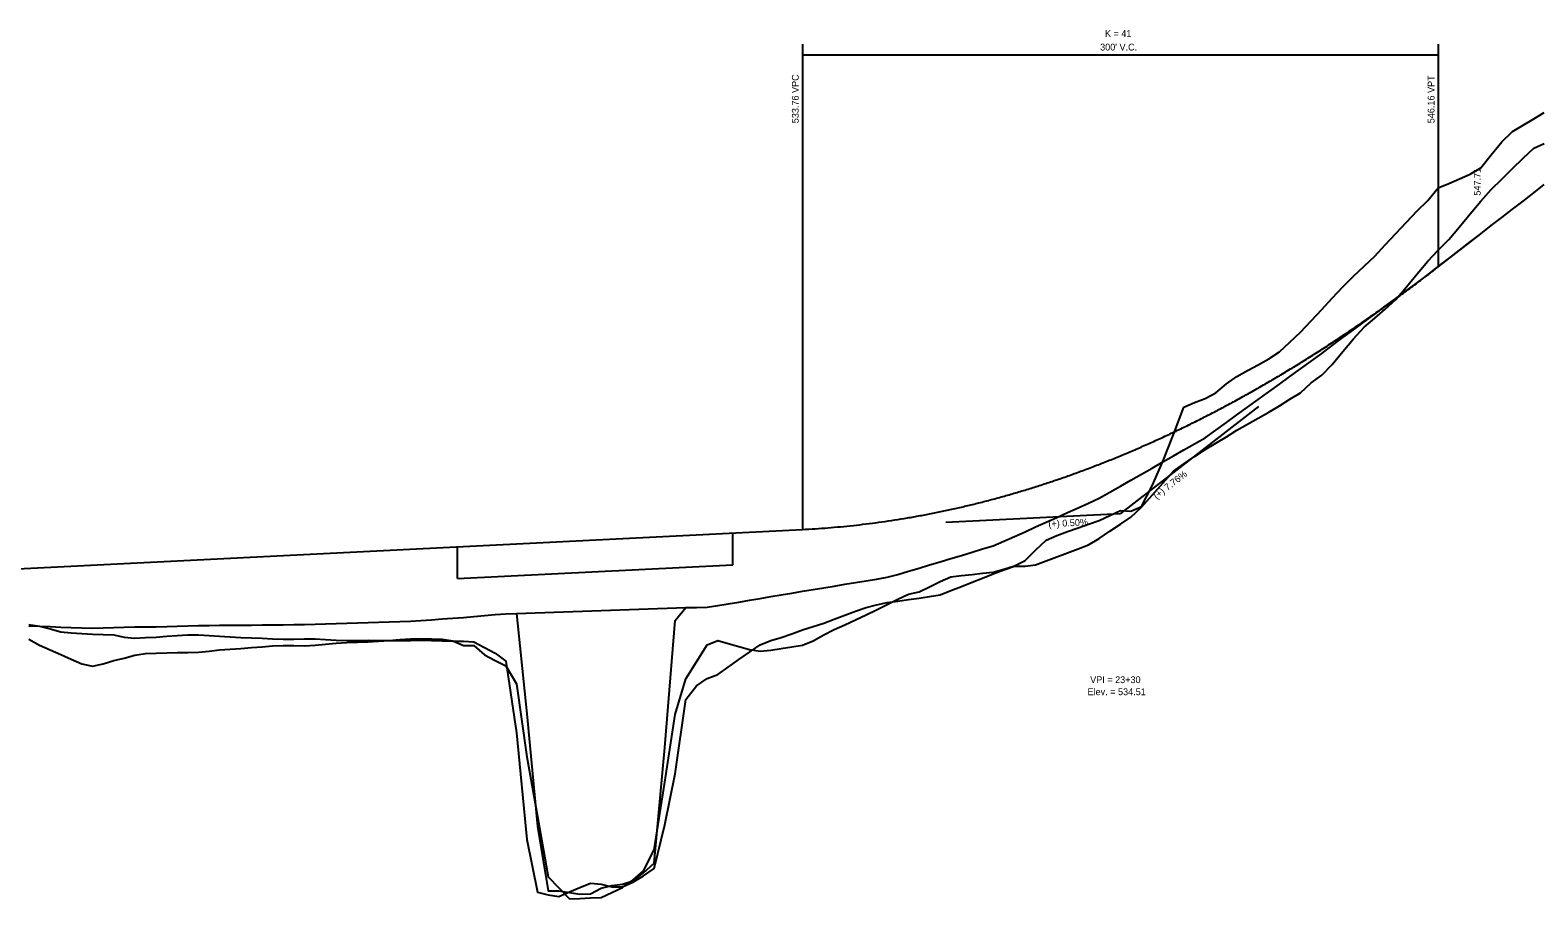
# Model space of a CAD drawing. Extents: x 1511486 to 1516886, y 901686 to 906985.
# Drawn here: x 1513890 to 1514602, y 905350 to 905760 of the extents above; entities that cross this region are included whole.
import ezdxf

# ---------------------------------------------------------------- set-up
doc = ezdxf.new("R2010")
doc.units = 0
for name, color, linetype in [('RD_DDB_GradeTX', 7, 'Continuous'), ('RD_DDB_Profile_EX', 7, 'Continuous'), ('RD_DDB_Profile_Lbl', 7, 'Continuous'), ('RD_DDB_Profile_PR', 7, 'Continuous'), ('RD_DDB_StripGrade', 7, 'Continuous'), ('RD_DDB_VCLbl', 7, 'Continuous'), ('RD_Sketch1', 7, 'Continuous'), ('RD_Sketch2', 7, 'Continuous'), ('RD_Sketch3', 7, 'Continuous')]:
    doc.layers.add(name, color=color, linetype=linetype)

msp = doc.modelspace()

# ---------------------------------------------------------------- linework, layer by layer
at = {"layer": 'RD_DDB_GradeTX'}
for p in [(1514469.77, 905582.08), (1514322.39, 905527.44)]:
    msp.add_line(p, (1514404.68, 905531.55), dxfattribs=at)
at = {"layer": 'RD_DDB_Profile_EX'}
for points in [[(1514574.68, 905663.52), (1514579.68, 905667.38), (1514584.68, 905671.23), (1514589.68, 905675.09), (1514594.68, 905678.97), (1514599.68, 905682.91), (1514604.68, 905686.86)], [(1514074.68, 905481.08), (1514079.68, 905481.48), (1514084.68, 905481.88), (1514089.68, 905482.21), (1514094.68, 905482.58), (1514099.68, 905482.99), (1514104.68, 905483.42), (1514109.68, 905483.86), (1514114.68, 905484.17), (1514119.68, 905484.46), (1514124.68, 905437.02), (1514129.68, 905383.98), (1514134.68, 905353.54), (1514139.68, 905353.56), (1514144.68, 905352.76), (1514149.68, 905351.96), (1514154.68, 905352.1), (1514159.68, 905354.75), (1514164.68, 905356.11), (1514169.68, 905356.62), (1514174.68, 905358.34), (1514179.68, 905361.97), (1514184.68, 905366.53), (1514189.68, 905421.12), (1514194.68, 905481.14), (1514199.68, 905487.19), (1514204.68, 905487.3), (1514209.68, 905487.41), (1514214.68, 905488.1), (1514219.68, 905488.96), (1514224.68, 905489.81), (1514229.68, 905490.66), (1514234.68, 905491.51), (1514239.68, 905492.36), (1514244.68, 905493.22), (1514249.68, 905494.04), (1514254.68, 905494.87), (1514259.68, 905495.69), (1514264.68, 905496.51), (1514269.68, 905497.34), (1514274.68, 905498.16), (1514279.68, 905498.98), (1514284.68, 905499.81), (1514289.68, 905500.63), (1514294.68, 905501.46), (1514299.68, 905502.83), (1514304.68, 905504.33), (1514309.68, 905505.83), (1514314.68, 905507.33), (1514319.68, 905508.83), (1514324.68, 905510.33), (1514329.68, 905511.83), (1514334.68, 905513.33), (1514339.68, 905514.83), (1514344.68, 905516.32), (1514349.68, 905518.46), (1514354.68, 905520.71), (1514359.68, 905522.97), (1514364.68, 905525.21), (1514369.68, 905527.47), (1514374.68, 905529.72), (1514379.68, 905531.98), (1514384.68, 905534.24), (1514389.68, 905536.5), (1514394.68, 905538.75), (1514399.68, 905541.56), (1514404.68, 905544.42), (1514409.68, 905547.28), (1514414.68, 905550.15), (1514419.68, 905553.01), (1514424.68, 905555.87), (1514429.68, 905558.74), (1514434.68, 905561.6), (1514439.68, 905564.46), (1514444.68, 905567.32), (1514449.68, 905570.88), (1514454.68, 905574.49), (1514459.68, 905578.11), (1514464.68, 905581.72), (1514469.68, 905585.33), (1514474.68, 905588.95), (1514479.68, 905592.56), (1514484.68, 905596.17), (1514489.68, 905599.79), (1514494.68, 905603.41), (1514499.68, 905607.13), (1514504.68, 905610.84), (1514509.68, 905614.54), (1514514.68, 905618.23), (1514519.68, 905621.93), (1514524.68, 905625.63), (1514529.68, 905629.34), (1514534.68, 905633.04), (1514539.68, 905636.74), (1514544.68, 905640.34), (1514549.68, 905644.2), (1514554.68, 905648.06), (1514559.68, 905651.92), (1514564.68, 905655.81), (1514569.68, 905659.67), (1514574.68, 905663.52)], [(1513889.68, 905478.58), (1513894.68, 905478.39), (1513899.68, 905478.2), (1513904.68, 905478), (1513909.68, 905477.79), (1513914.68, 905477.58), (1513919.68, 905477.53), (1513924.68, 905477.61), (1513929.68, 905477.79), (1513934.68, 905477.95), (1513939.68, 905478.03), (1513944.68, 905478.05), (1513949.68, 905478.18), (1513954.68, 905478.31), (1513959.68, 905478.44), (1513964.68, 905478.56), (1513969.68, 905478.67), (1513974.68, 905478.76), (1513979.68, 905478.83), (1513984.68, 905478.9), (1513989.68, 905478.89), (1513994.68, 905478.95), (1513999.68, 905479.01), (1514004.68, 905479.06), (1514009.68, 905479.11), (1514014.68, 905479.16), (1514019.68, 905479.2), (1514024.68, 905479.31), (1514029.68, 905479.46), (1514034.68, 905479.62), (1514039.68, 905479.79), (1514044.68, 905479.95), (1514049.68, 905480.1), (1514054.68, 905480.26), (1514059.68, 905480.41), (1514064.68, 905480.57), (1514069.68, 905480.72), (1514074.68, 905481.08)]]:
    msp.add_lwpolyline(points, dxfattribs=at)
at = {"layer": 'RD_DDB_Profile_PR'}
for p, q in [((1514554.68, 905648), (1514574.68, 905663.52)), ((1513874.68, 905505.05), (1514254.68, 905524.05))]:
    msp.add_line(p, q, dxfattribs=at)
msp.add_spline([(1514254.68, 905524.05), (1514260.68, 905524.4), (1514266.68, 905524.83), (1514272.68, 905525.35), (1514278.68, 905525.95), (1514284.68, 905526.64), (1514290.68, 905527.42), (1514296.68, 905528.29), (1514302.68, 905529.24), (1514308.68, 905530.28), (1514314.68, 905531.41), (1514320.68, 905532.63), (1514326.68, 905533.93), (1514332.68, 905535.32), (1514338.68, 905536.8), (1514344.68, 905538.36), (1514350.68, 905540.01), (1514356.68, 905541.75), (1514362.68, 905543.57), (1514368.68, 905545.49), (1514374.68, 905547.49), (1514380.68, 905549.57), (1514386.68, 905551.75), (1514392.68, 905554.01), (1514398.68, 905556.36), (1514404.68, 905558.79), (1514410.68, 905561.31), (1514416.68, 905563.92), (1514422.68, 905566.62), (1514428.68, 905569.4), (1514434.68, 905572.27), (1514440.68, 905575.23), (1514446.68, 905578.28), (1514452.68, 905581.41), (1514458.68, 905584.63), (1514464.68, 905587.94), (1514470.68, 905591.33), (1514476.68, 905594.81), (1514482.68, 905598.38), (1514488.68, 905602.04), (1514494.68, 905605.78), (1514500.68, 905609.61), (1514506.68, 905613.53), (1514512.68, 905617.53), (1514518.68, 905621.62), (1514524.68, 905625.8), (1514530.68, 905630.07), (1514536.68, 905634.42), (1514542.68, 905638.86), (1514548.68, 905643.38), (1514554.68, 905648)], degree=3, dxfattribs=at)
at = {"layer": 'RD_DDB_VCLbl'}
for p, q in [((1514254.68, 905753), (1514254.68, 905524.05)), ((1514554.68, 905753), (1514554.68, 905648)), ((1514254.68, 905748), (1514554.68, 905748))]:
    msp.add_line(p, q, dxfattribs=at)
at = {"layer": 'RD_Sketch1'}
msp.add_line((1514119.68, 905484.46), (1514199.68, 905487.19), dxfattribs=at)
at = {"layer": 'RD_Sketch2'}
for points in [[(1514574.68, 905694.6), (1514579.68, 905700.74), (1514584.68, 905706.87), (1514589.68, 905711.72), (1514594.68, 905714.75), (1514599.68, 905717.77), (1514604.68, 905720.79)], [(1514574.68, 905678.94), (1514579.68, 905684.36), (1514584.68, 905689.33), (1514589.68, 905694.3), (1514594.68, 905699.22), (1514599.68, 905703.94), (1514604.68, 905706.13)], [(1514074.68, 905472.66), (1514079.68, 905472.51), (1514084.68, 905472.24), (1514089.68, 905471.5), (1514094.68, 905469.22), (1514099.68, 905469.22), (1514104.68, 905464.87), (1514109.68, 905462.24), (1514114.68, 905459.73), (1514119.68, 905451.22), (1514124.68, 905416.76), (1514129.68, 905388.67), (1514134.68, 905360.19), (1514139.68, 905354.97), (1514144.68, 905349.77), (1514149.68, 905350.01), (1514154.68, 905350.23), (1514159.68, 905350.38), (1514164.68, 905352.72), (1514169.68, 905355.05), (1514174.68, 905358.52), (1514179.68, 905363.02), (1514184.68, 905372.97), (1514189.68, 905404.89), (1514194.68, 905436.81), (1514199.68, 905453.55), (1514204.68, 905461.61), (1514209.68, 905469.67), (1514214.68, 905471.69), (1514219.68, 905470.26), (1514224.68, 905468.82), (1514229.68, 905467.39), (1514234.68, 905466.57), (1514239.68, 905467.15), (1514244.68, 905467.84), (1514249.68, 905468.63), (1514254.68, 905469.43), (1514259.68, 905471.44), (1514264.68, 905474.35), (1514269.68, 905476.78), (1514274.68, 905479.12), (1514279.68, 905481.47), (1514284.68, 905483.82), (1514289.68, 905486.17), (1514294.68, 905488.59), (1514299.68, 905491.19), (1514304.68, 905493.48), (1514309.68, 905494.55), (1514314.68, 905497.02), (1514319.68, 905499.49), (1514324.68, 905501.74), (1514329.68, 905502.3), (1514334.68, 905502.86), (1514339.68, 905503.41), (1514344.68, 905503.97), (1514349.68, 905505.36), (1514354.68, 905506.94), (1514359.68, 905509.47), (1514364.68, 905514.22), (1514369.68, 905518.97), (1514374.68, 905521.26), (1514379.68, 905523.02), (1514384.68, 905524.78), (1514389.68, 905526.54), (1514394.68, 905528.3), (1514399.68, 905530.65), (1514404.68, 905533.04), (1514409.68, 905532.67), (1514414.68, 905534.94), (1514419.68, 905544.64), (1514424.68, 905556.08), (1514429.68, 905568.9), (1514434.68, 905581.72), (1514439.68, 905583.99), (1514444.68, 905585.79), (1514449.68, 905588.43), (1514454.68, 905592.73), (1514459.68, 905596.24), (1514464.68, 905599), (1514469.68, 905601.75), (1514474.68, 905604.5), (1514479.68, 905607.89), (1514484.68, 905612.46), (1514489.68, 905617.08), (1514494.68, 905622.45), (1514499.68, 905627.81), (1514504.68, 905633.18), (1514509.68, 905638.54), (1514514.68, 905643.46), (1514519.68, 905648.23), (1514524.68, 905652.99), (1514529.68, 905658.25), (1514534.68, 905663.62), (1514539.68, 905668.99), (1514544.68, 905674.37), (1514549.68, 905679.24), (1514554.68, 905685.16), (1514559.68, 905687.33), (1514564.68, 905689.49), (1514569.68, 905691.66), (1514574.68, 905694.6)], [(1514074.68, 905471.79), (1514079.68, 905471.64), (1514084.68, 905471.5), (1514089.68, 905471.4), (1514094.68, 905471.35), (1514099.68, 905471.01), (1514104.68, 905468.29), (1514109.68, 905465.68), (1514114.68, 905461.91), (1514119.68, 905428.12), (1514124.68, 905377.81), (1514129.68, 905352.9), (1514134.68, 905351.65), (1514139.68, 905350.85), (1514144.68, 905353.01), (1514149.68, 905355.12), (1514154.68, 905357.21), (1514159.68, 905356.72), (1514164.68, 905355.51), (1514169.68, 905355.48), (1514174.68, 905357.64), (1514179.68, 905360.63), (1514184.68, 905364.03), (1514189.68, 905384.69), (1514194.68, 905408.68), (1514199.68, 905443.88), (1514204.68, 905450.29), (1514209.68, 905453.78), (1514214.68, 905455.66), (1514219.68, 905459.14), (1514224.68, 905462.62), (1514229.68, 905466.1), (1514234.68, 905469.58), (1514239.68, 905471.7), (1514244.68, 905473.06), (1514249.68, 905474.79), (1514254.68, 905476.72), (1514259.68, 905478.24), (1514264.68, 905479.86), (1514269.68, 905481.71), (1514274.68, 905483.57), (1514279.68, 905485.42), (1514284.68, 905487.27), (1514289.68, 905488.52), (1514294.68, 905489.59), (1514299.68, 905490.27), (1514304.68, 905490.94), (1514309.68, 905491.62), (1514314.68, 905492.4), (1514319.68, 905493.27), (1514324.68, 905495.23), (1514329.68, 905497.19), (1514334.68, 905499.16), (1514339.68, 905501.12), (1514344.68, 905503.07), (1514349.68, 905504.98), (1514354.68, 905506.8), (1514359.68, 905506.68), (1514364.68, 905507.38), (1514369.68, 905509.25), (1514374.68, 905511.13), (1514379.68, 905513.01), (1514384.68, 905514.88), (1514389.68, 905516.76), (1514394.68, 905519.77), (1514399.68, 905523.31), (1514404.68, 905526.57), (1514409.68, 905529.83), (1514414.68, 905534.61), (1514419.68, 905540.26), (1514424.68, 905545.9), (1514429.68, 905551.54), (1514434.68, 905555.07), (1514439.68, 905558.43), (1514444.68, 905561.79), (1514449.68, 905564.79), (1514454.68, 905567.78), (1514459.68, 905570.86), (1514464.68, 905573.71), (1514469.68, 905576.53), (1514474.68, 905579.36), (1514479.68, 905582.39), (1514484.68, 905585.46), (1514489.68, 905588.53), (1514494.68, 905593.14), (1514499.68, 905596.79), (1514504.68, 905601.92), (1514509.68, 905607.97), (1514514.68, 905614.02), (1514519.68, 905619.45), (1514524.68, 905623.7), (1514529.68, 905627.96), (1514534.68, 905632.5), (1514539.68, 905638.55), (1514544.68, 905644.59), (1514549.68, 905650.63), (1514554.68, 905655.8), (1514559.68, 905660.81), (1514564.68, 905666.86), (1514569.68, 905672.9), (1514574.68, 905678.94)], [(1513889.68, 905479.13), (1513894.68, 905478.38), (1513899.68, 905477.08), (1513904.68, 905475.75), (1513909.68, 905475.2), (1513914.68, 905474.88), (1513919.68, 905474.59), (1513924.68, 905474.44), (1513929.68, 905474.35), (1513934.68, 905473.3), (1513939.68, 905472.81), (1513944.68, 905473.02), (1513949.68, 905473.3), (1513954.68, 905473.63), (1513959.68, 905474.02), (1513964.68, 905474.35), (1513969.68, 905474.35), (1513974.68, 905474), (1513979.68, 905473.67), (1513984.68, 905473.36), (1513989.68, 905473.14), (1513994.68, 905472.9), (1513999.68, 905472.68), (1514004.68, 905472.48), (1514009.68, 905472.31), (1514014.68, 905472.23), (1514019.68, 905472.39), (1514024.68, 905472.41), (1514029.68, 905472.13), (1514034.68, 905471.89), (1514039.68, 905471.68), (1514044.68, 905471.64), (1514049.68, 905471.79), (1514054.68, 905471.7), (1514059.68, 905471.66), (1514064.68, 905471.66), (1514069.68, 905471.71), (1514074.68, 905471.79)], [(1513889.68, 905472.24), (1513894.68, 905469.44), (1513899.68, 905467.23), (1513904.68, 905465.05), (1513909.68, 905462.87), (1513914.68, 905460.68), (1513919.68, 905459.49), (1513924.68, 905460.67), (1513929.68, 905462.18), (1513934.68, 905463.39), (1513939.68, 905464.69), (1513944.68, 905465.5), (1513949.68, 905465.69), (1513954.68, 905465.85), (1513959.68, 905465.96), (1513964.68, 905466.04), (1513969.68, 905466.09), (1513974.68, 905466.68), (1513979.68, 905467.25), (1513984.68, 905467.51), (1513989.68, 905467.88), (1513994.68, 905468.31), (1513999.68, 905468.71), (1514004.68, 905469.06), (1514009.68, 905469.35), (1514014.68, 905469.29), (1514019.68, 905469.21), (1514024.68, 905469.43), (1514029.68, 905469.9), (1514034.68, 905470.34), (1514039.68, 905470.75), (1514044.68, 905470.91), (1514049.68, 905471.02), (1514054.68, 905471.39), (1514059.68, 905471.73), (1514064.68, 905472.06), (1514069.68, 905472.37), (1514074.68, 905472.66)]]:
    msp.add_lwpolyline(points, dxfattribs=at)
at = {"layer": 'RD_Sketch3'}
for p, q in [((1514221.83, 905507.39), (1514221.83, 905522.41)), ((1514091.83, 905500.89), (1514091.83, 905515.91)), ((1514091.83, 905500.89), (1514221.83, 905507.39))]:
    msp.add_line(p, q, dxfattribs=at)

# ---------------------------------------------------------------- texts
at = {"layer": 'RD_DDB_GradeTX'}
for s, rotation, p in [('(+) 7.76%', 37.82194, (1514421.76, 905538.15)), ('(+) 0.50%', 2.86241, (1514370.8, 905525.04))]:
    msp.add_text(s, height=3.2, rotation=rotation, dxfattribs=at).set_placement(p)
at = {"layer": 'RD_DDB_Profile_Lbl'}
msp.add_text('547.71', height=3.2, rotation=90, dxfattribs=at).set_placement((1514574.68, 905681.52))
for s, p in [('VPI = 23+30', (1514390.43, 905451.55)), ('Elev. = 534.51', (1514389.17, 905445.86))]:
    msp.add_text(s, height=3.2, dxfattribs=at).set_placement(p)
at = {"layer": 'RD_DDB_StripGrade'}
for s, p in [('533.76 VPC', (1514252.89, 905715.68)), ('546.16 VPT', (1514552.89, 905715.68))]:
    msp.add_text(s, height=3.2, rotation=90, dxfattribs=at).set_placement(p)
at = {"layer": 'RD_DDB_VCLbl'}
for s, p in [('K = 41', (1514397.4, 905756.4)), ("300' V.C.", (1514395.12, 905750))]:
    msp.add_text(s, height=3.2, dxfattribs=at).set_placement(p)

doc.saveas('drawing.dxf')
